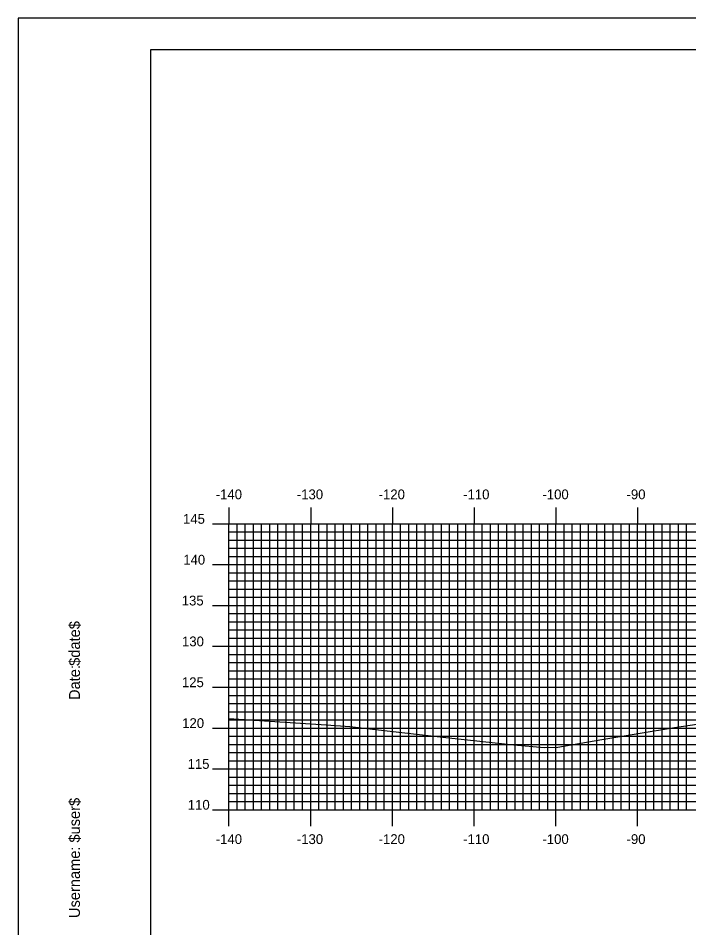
# Model space of a CAD drawing. Extents: x 852934 to 853277, y 364661 to 364881.
# Drawn here: x 852934 to 853016, y 364769.9 to 364881.3 of the extents above; entities that cross this region are included whole.
import ezdxf

# ---------------------------------------------------------------- set-up
doc = ezdxf.new("R2010")
doc.units = 0
for name, color, linetype in [('BORDER', 7, 'Continuous'), ('H_V ANNOTATION', 7, 'Continuous'), ('MAJOR', 7, 'Continuous'), ('MINOR', 7, 'Continuous'), ('PLOT BOUNDARY', 7, 'Continuous'), ('S_Roadway_Centerline', 7, 'Continuous')]:
    doc.layers.add(name, color=color, linetype=linetype)

msp = doc.modelspace()

# ---------------------------------------------------------------- linework, layer by layer
at = {"layer": 'BORDER'}
msp.add_lwpolyline([(852950.18, 364667.37), (853270.18, 364667.37), (853270.18, 364877.37), (852950.18, 364877.37)], close=True, dxfattribs=at)
at = {"layer": 'MAJOR'}
for p, q in [((852959.78, 364821.37), (852959.78, 364819.37)), ((852969.78, 364821.37), (852969.78, 364819.37)), ((852979.78, 364821.37), (852979.78, 364819.37)), ((852989.78, 364821.37), (852989.78, 364819.37)), ((852999.78, 364821.37), (852999.78, 364819.37)), ((853009.78, 364821.37), (853009.78, 364819.37)), ((852957.78, 364819.37), (852959.78, 364819.37)), ((852959.78, 364819.37), (853239.78, 364819.37)), ((852959.78, 364784.37), (852959.78, 364819.37)), ((852959.78, 364784.37), (852959.78, 364819.37)), ((852959.78, 364819.37), (853239.78, 364819.37)), ((852969.78, 364784.37), (852969.78, 364819.37)), ((852979.78, 364784.37), (852979.78, 364819.37)), ((852989.78, 364784.37), (852989.78, 364819.37)), ((852999.78, 364784.37), (852999.78, 364819.37)), ((853009.78, 364784.37), (853009.78, 364819.37)), ((852957.78, 364814.37), (852959.78, 364814.37)), ((852959.78, 364814.37), (853239.78, 364814.37)), ((852957.78, 364809.37), (852959.78, 364809.37)), ((852959.78, 364809.37), (853239.78, 364809.37)), ((852957.78, 364804.37), (852959.78, 364804.37)), ((852959.78, 364804.37), (853239.78, 364804.37)), ((852957.78, 364799.37), (852959.78, 364799.37)), ((852959.78, 364799.37), (853239.78, 364799.37)), ((852957.78, 364794.37), (852959.78, 364794.37)), ((852959.78, 364794.37), (853239.78, 364794.37)), ((852957.78, 364789.37), (852959.78, 364789.37)), ((852959.78, 364789.37), (853239.78, 364789.37)), ((852957.78, 364784.37), (852959.78, 364784.37)), ((852959.78, 364784.37), (853239.78, 364784.37)), ((852959.78, 364784.37), (853239.78, 364784.37)), ((852959.78, 364782.37), (852959.78, 364784.37)), ((852969.78, 364782.37), (852969.78, 364784.37)), ((852979.78, 364782.37), (852979.78, 364784.37)), ((852989.78, 364782.37), (852989.78, 364784.37)), ((852999.78, 364782.37), (852999.78, 364784.37)), ((853009.78, 364782.37), (853009.78, 364784.37))]:
    msp.add_line(p, q, dxfattribs=at)
at = {"layer": 'MINOR'}
for p, q in [((852960.78, 364784.37), (852960.78, 364819.37)), ((852961.78, 364784.37), (852961.78, 364819.37)), ((852962.78, 364784.37), (852962.78, 364819.37)), ((852963.78, 364784.37), (852963.78, 364819.37)), ((852964.78, 364784.37), (852964.78, 364819.37)), ((852965.78, 364784.37), (852965.78, 364819.37)), ((852966.78, 364784.37), (852966.78, 364819.37)), ((852967.78, 364784.37), (852967.78, 364819.37)), ((852968.78, 364784.37), (852968.78, 364819.37)), ((852970.78, 364784.37), (852970.78, 364819.37)), ((852971.78, 364784.37), (852971.78, 364819.37)), ((852972.78, 364784.37), (852972.78, 364819.37)), ((852973.78, 364784.37), (852973.78, 364819.37)), ((852974.78, 364784.37), (852974.78, 364819.37)), ((852975.78, 364784.37), (852975.78, 364819.37)), ((852976.78, 364784.37), (852976.78, 364819.37)), ((852977.78, 364784.37), (852977.78, 364819.37)), ((852978.78, 364784.37), (852978.78, 364819.37)), ((852980.78, 364784.37), (852980.78, 364819.37)), ((852981.78, 364784.37), (852981.78, 364819.37)), ((852982.78, 364784.37), (852982.78, 364819.37)), ((852983.78, 364784.37), (852983.78, 364819.37)), ((852984.78, 364784.37), (852984.78, 364819.37)), ((852985.78, 364784.37), (852985.78, 364819.37)), ((852986.78, 364784.37), (852986.78, 364819.37)), ((852987.78, 364784.37), (852987.78, 364819.37)), ((852988.78, 364784.37), (852988.78, 364819.37)), ((852990.78, 364784.37), (852990.78, 364819.37)), ((852991.78, 364784.37), (852991.78, 364819.37)), ((852992.78, 364784.37), (852992.78, 364819.37)), ((852993.78, 364784.37), (852993.78, 364819.37)), ((852994.78, 364784.37), (852994.78, 364819.37)), ((852995.78, 364784.37), (852995.78, 364819.37)), ((852996.78, 364784.37), (852996.78, 364819.37)), ((852997.78, 364784.37), (852997.78, 364819.37)), ((852998.78, 364784.37), (852998.78, 364819.37)), ((853000.78, 364784.37), (853000.78, 364819.37)), ((853001.78, 364784.37), (853001.78, 364819.37)), ((853002.78, 364784.37), (853002.78, 364819.37)), ((853003.78, 364784.37), (853003.78, 364819.37)), ((853004.78, 364784.37), (853004.78, 364819.37)), ((853005.78, 364784.37), (853005.78, 364819.37)), ((853006.78, 364784.37), (853006.78, 364819.37)), ((853007.78, 364784.37), (853007.78, 364819.37)), ((853008.78, 364784.37), (853008.78, 364819.37)), ((853010.78, 364784.37), (853010.78, 364819.37)), ((853011.78, 364784.37), (853011.78, 364819.37)), ((853012.78, 364784.37), (853012.78, 364819.37)), ((853013.78, 364784.37), (853013.78, 364819.37)), ((853014.78, 364784.37), (853014.78, 364819.37)), ((853015.78, 364784.37), (853015.78, 364819.37)), ((852959.78, 364818.37), (853239.78, 364818.37)), ((852959.78, 364818.37), (852961.79, 364818.37)), ((852959.78, 364817.37), (853239.78, 364817.37)), ((852959.78, 364817.37), (852961.79, 364817.37)), ((852959.78, 364816.37), (853239.78, 364816.37)), ((852959.78, 364816.37), (852961.79, 364816.37)), ((852959.78, 364815.37), (853239.78, 364815.37)), ((852959.78, 364815.37), (852961.79, 364815.37)), ((852959.78, 364813.37), (853239.78, 364813.37)), ((852959.78, 364813.37), (852961.79, 364813.37)), ((852959.78, 364812.37), (853239.78, 364812.37)), ((852959.78, 364812.37), (852961.79, 364812.37)), ((852959.78, 364811.37), (853239.78, 364811.37)), ((852959.78, 364811.37), (852961.79, 364811.37)), ((852959.78, 364810.37), (853239.78, 364810.37)), ((852959.78, 364810.37), (852961.79, 364810.37)), ((852959.78, 364808.37), (853239.78, 364808.37)), ((852959.78, 364808.37), (852961.79, 364808.37)), ((852959.78, 364807.37), (853239.78, 364807.37)), ((852959.78, 364807.37), (852961.79, 364807.37)), ((852959.78, 364806.37), (853239.78, 364806.37)), ((852959.78, 364806.37), (852961.79, 364806.37)), ((852959.78, 364805.37), (853239.78, 364805.37)), ((852959.78, 364805.37), (852961.79, 364805.37)), ((852959.78, 364803.37), (853239.78, 364803.37)), ((852959.78, 364803.37), (852961.79, 364803.37)), ((852959.78, 364802.37), (853239.78, 364802.37)), ((852959.78, 364802.37), (852961.79, 364802.37)), ((852959.78, 364801.37), (853239.78, 364801.37)), ((852959.78, 364801.37), (852961.79, 364801.37)), ((852959.78, 364800.37), (853239.78, 364800.37)), ((852959.78, 364800.37), (852961.79, 364800.37)), ((852959.78, 364798.37), (853239.78, 364798.37)), ((852959.78, 364798.37), (852961.79, 364798.37)), ((852959.78, 364797.37), (853239.78, 364797.37)), ((852959.78, 364797.37), (852961.79, 364797.37)), ((852959.78, 364796.37), (853239.78, 364796.37)), ((852959.78, 364796.37), (852961.79, 364796.37)), ((852959.78, 364795.37), (853239.78, 364795.37)), ((852959.78, 364795.37), (852961.79, 364795.37)), ((852959.78, 364793.37), (853239.78, 364793.37)), ((852959.78, 364793.37), (852961.79, 364793.37)), ((852959.78, 364792.37), (853239.78, 364792.37)), ((852959.78, 364792.37), (852961.79, 364792.37)), ((852959.78, 364791.37), (853239.78, 364791.37)), ((852959.78, 364791.37), (852961.79, 364791.37)), ((852959.78, 364790.37), (853239.78, 364790.37)), ((852959.78, 364790.37), (852961.79, 364790.37)), ((852959.78, 364788.37), (853239.78, 364788.37)), ((852959.78, 364788.37), (852961.79, 364788.37)), ((852959.78, 364787.37), (853239.78, 364787.37)), ((852959.78, 364787.37), (852961.79, 364787.37)), ((852959.78, 364786.37), (853239.78, 364786.37)), ((852959.78, 364786.37), (852961.79, 364786.37)), ((852959.78, 364785.37), (853239.78, 364785.37)), ((852959.78, 364785.37), (852961.79, 364785.37))]:
    msp.add_line(p, q, dxfattribs=at)
at = {"layer": 'PLOT BOUNDARY'}
msp.add_lwpolyline([(852933.99, 364661.25), (853273.99, 364661.25), (853273.99, 364881.25), (852933.99, 364881.25)], close=True, dxfattribs=at)
at = {"layer": 'S_Roadway_Centerline'}
msp.add_lwpolyline([(852959.78, 364795.55), (852962.27, 364795.38), (852971.68, 364794.77), (852974.56, 364794.54), (852977.71, 364794.17), (852986.69, 364793.17), (852994.63, 364792.33), (852998.36, 364792), (853000.04, 364792.04), (853005.41, 364792.96), (853014.3, 364794.43), (853020.03, 364795.3)], dxfattribs=at)

# ---------------------------------------------------------------- texts
at = {"layer": 'BORDER'}
for s, p in [('$date$', (852941.55, 364801.98)), ('Date:', (852941.55, 364797.8)), ('$user$', (852941.55, 364780.35)), ('Username:', (852941.55, 364771.11))]:
    msp.add_text(s, height=1.339, rotation=90, dxfattribs=at).set_placement(p)
at = {"layer": 'H_V ANNOTATION'}
for s, p in [('-140', (852958.17, 364822.37)), ('-130', (852968.09, 364822.37)), ('-120', (852978.1, 364822.37)), ('-110', (852988.44, 364822.37)), ('-100', (852998.14, 364822.37)), ('-90', (853008.43, 364822.37)), ('145', (852954.16, 364819.37)), ('140', (852954.19, 364814.37)), ('135', (852954.01, 364809.37)), ('130', (852954.04, 364804.37)), ('125', (852954.03, 364799.37)), ('120', (852954.06, 364794.37)), ('115', (852954.72, 364789.37)), ('110', (852954.75, 364784.37)), ('-140', (852958.17, 364780.17)), ('-130', (852968.09, 364780.17)), ('-120', (852978.1, 364780.17)), ('-110', (852988.44, 364780.17)), ('-100', (852998.14, 364780.17)), ('-90', (853008.43, 364780.17))]:
    msp.add_text(s, height=1.2, dxfattribs=at).set_placement(p)
at = {"layer": 'MAJOR'}
msp.add_text('-', height=0.012, dxfattribs=at).set_placement((852959.77, 364784.37))

doc.saveas('drawing.dxf')
